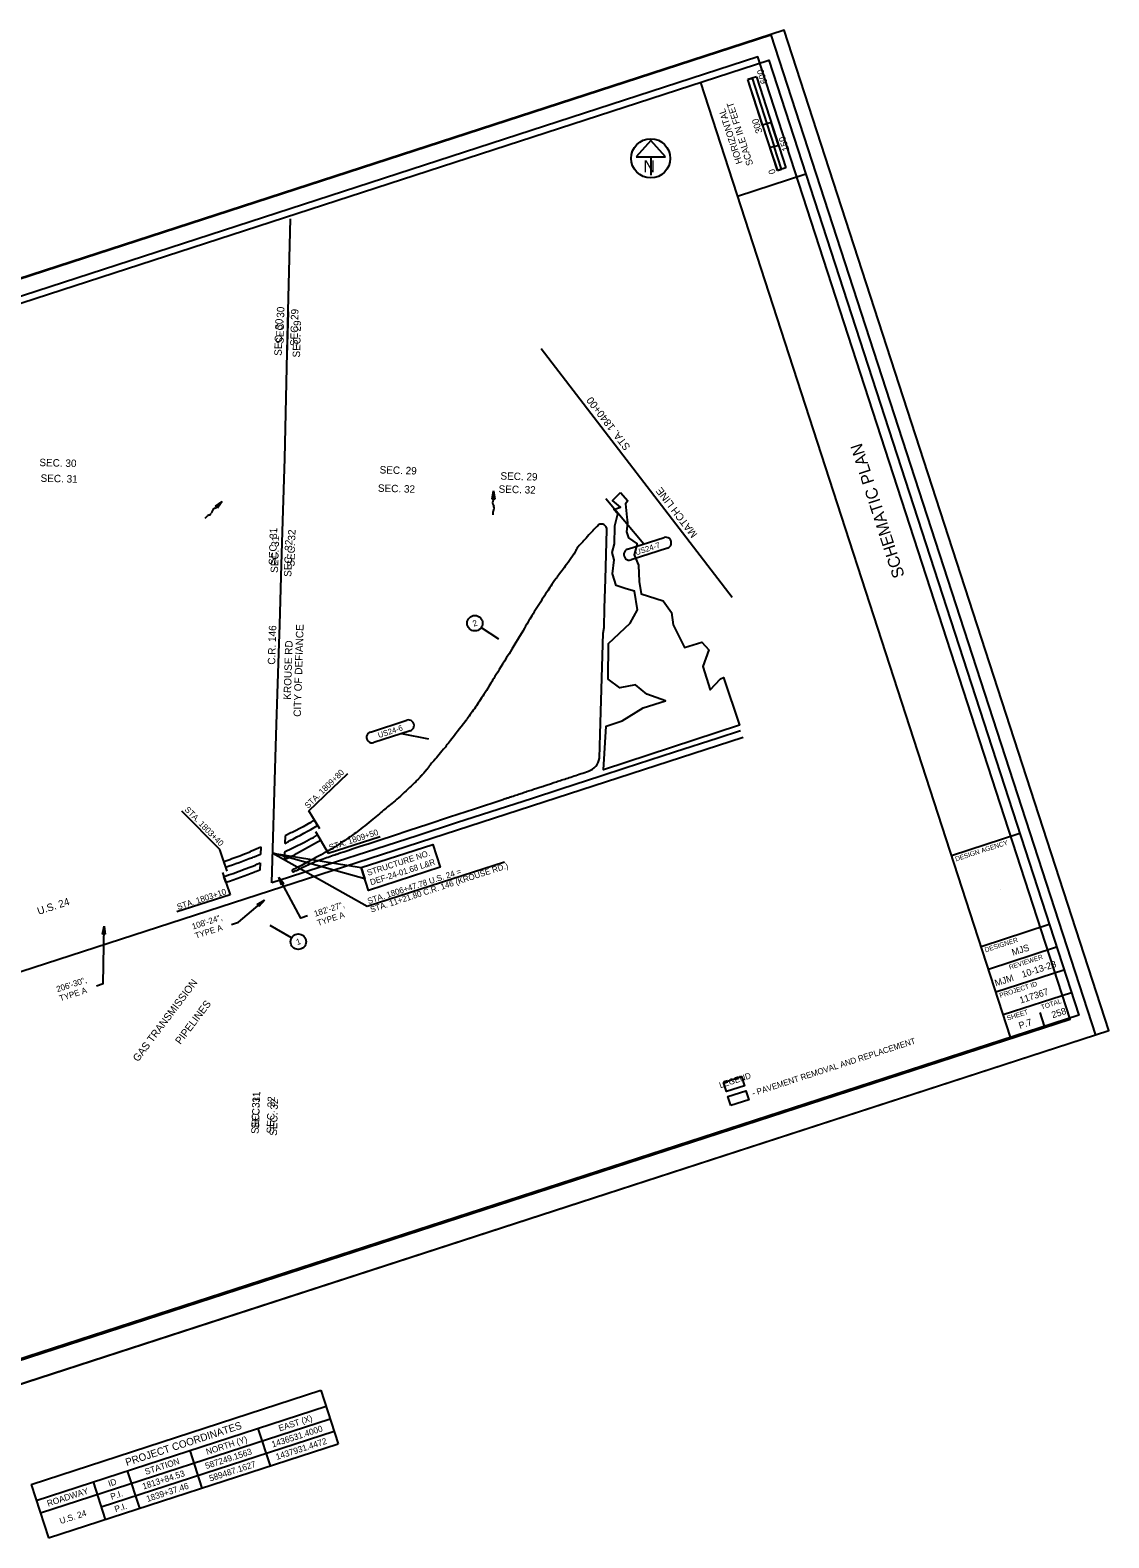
# Model space of a CAD drawing. Extents: x -347516349 to 1482925, y -281753163 to 592205.
# Drawn here: x 1434301 to 1441073, y 582744 to 592205 of the extents above; entities that cross this region are included whole.
import ezdxf

# ---------------------------------------------------------------- set-up
doc = ezdxf.new("R2010")
doc.units = 0
for name, color, linetype in [('DV_X_County_Line', 7, 'Continuous'), ('Level 31', 7, 'Continuous'), ('Level 63', 7, 'Continuous'), ('RD_X_Fence', 7, 'Continuous'), ('RD_X_RR_1', 7, 'Continuous'), ('RW_X_CL', 7, 'Continuous'), ('RW_X_Esmt_CH', 7, 'Continuous'), ('RW_X_Esmt_General', 7, 'Continuous'), ('RW_X_Esmt_LA', 7, 'Continuous'), ('RW_X_Esmt_PB', 7, 'Continuous'), ('RW_X_Fee_RW', 7, 'Continuous'), ('SC_Shading2', 7, 'Continuous'), ('SH_Masking', 7, 'Continuous')]:
    doc.layers.add(name, color=color, linetype=linetype)

msp = doc.modelspace()

# ---------------------------------------------------------------- linework, layer by layer
at = {"layer": 'Level 31'}
for p, q in [((1435464.3, 589216.7), (1435506.9, 589247.1)), ((1435469.4, 589209.6), (1435506.9, 589247.1)), ((1435506.9, 589247.1), (1435476.5, 589204.5)), ((1437201.2, 589262.2), (1437210.9, 589313.6)), ((1437218.3, 589261.9), (1437201.2, 589262.2)), ((1437207.9, 589252.1), (1437206.1, 589248.1)), ((1437209.7, 589260.7), (1437210.9, 589313.6)), ((1437210.9, 589313.6), (1437218.3, 589261.9)), ((1435400.4, 589141.4), (1435415.2, 589156.2)), ((1435426.4, 589162.2), (1435422, 589160.6)), ((1435442.4, 589182.3), (1435439.3, 589174.7)), ((1435446, 589191), (1435442.4, 589182.3)), ((1435462.2, 589204.7), (1435458.1, 589203)), ((1435476.5, 589204.5), (1435464.3, 589216.7)), ((1437205.7, 589231), (1437209.1, 589222.3)), ((1437207.1, 589163.6), (1437207.5, 589184.6)), ((1437209.1, 589222.3), (1437212.1, 589214.6)), ((1437211.4, 589196.7), (1437209.4, 589192.5))]:
    msp.add_line(p, q, dxfattribs=at)
for centre, radius, start, end in [((1437226.6, 589239.1), 22.4, 156.37702, 201.22088), ((1437187.3, 589261.1), 22.4, 336.41585, 358.77587), ((1435428.8, 589142.6), 19.2, 110.52773, 135.01055), ((1435418.6, 589183.2), 22.4, 290.47786, 337.58632), ((1435466.7, 589182.4), 22.4, 112.61169, 157.45555), ((1435453.6, 589225.4), 22.4, 292.65053, 315.01055), ((1437226.7, 589184.2), 19.2, 154.29306, 178.77587), ((1437191.3, 589206.4), 22.4, 334.24318, 21.35164)]:
    msp.add_arc(centre, radius, start, end, dxfattribs=at)
at = {"layer": 'Level 63'}
for points in [[(1429250.2, 589026.2), (1438951, 592175.6), (1440988.8, 585898.9), (1431288, 582749.5)], [(1431356.9, 582923.2), (1440830.2, 585998.8), (1438870, 592036.6), (1429396.7, 588961)]]:
    msp.add_lwpolyline(points, close=True, dxfattribs=at)
at = {"layer": 'RD_X_Fence'}
for p, q in [((1437898, 588420.2), (1437904.1, 588457.1)), ((1436040.3, 586982.6), (1436008.2, 586965.4))]:
    msp.add_line(p, q, dxfattribs=at)
for points in [[(1438007.3, 589304.1), (1438053.9, 589251.1), (1438037.9, 589231.8), (1438048.1, 589147.8), (1438051, 589115.4), (1438044.5, 589056.3), (1438058.4, 589018.6), (1438112.5, 588981.1), (1438093.9, 588913.2), (1438119.4, 588847.8), (1438123.6, 588745.5), (1438137.9, 588668.4), (1438274.5, 588623.4), (1438327.9, 588550), (1438337.9, 588473.4), (1438409.5, 588330), (1438517.9, 588365), (1438561.2, 588316.7), (1438524.5, 588211.7), (1438569.5, 588065), (1438634.5, 588133.4), (1438654, 588141.8), (1438654, 588141.8), (1438654, 588141.8), (1438654, 588141.8), (1438654, 588141.8), (1438753.5, 587842.9), (1438753.5, 587842.9), (1438753.5, 587842.9), (1438753.5, 587842.9), (1437899.9, 587562.5), (1437899.9, 587562.5), (1437899.9, 587562.5), (1437899.9, 587562.5), (1437899.9, 587562.5), (1437899.9, 587562.5), (1437916.6, 587837.1), (1438018.7, 587870.5), (1438149.9, 587951.7), (1438289.5, 587995.5), (1438172.9, 588037.1), (1438102, 588095.5), (1438004.1, 588076.7), (1437929.1, 588133), (1437931.2, 588355.9), (1438068.7, 588483), (1438114.5, 588566.3), (1438096.2, 588685), (1438042.9, 588698.4), (1438043.8, 588698.9), (1437980.5, 588719.3), (1437958.1, 588793), (1437966.7, 588880.7), (1437954.1, 588926.2), (1437970.3, 588981.9), (1437972.4, 589090.4), (1437972.5, 589093.4), (1437991.2, 589168.6), (1437964.7, 589196), (1438007.2, 589211.6), (1437957.1, 589253.8), (1438007.3, 589304.1), (1438007.3, 589304.1)], [(1438653.6, 585600.7), (1438767.7, 585637.7), (1438767.7, 585637.7), (1438767.7, 585637.7), (1438767.7, 585637.7), (1438767.7, 585637.7), (1438786.2, 585580.7), (1438786.2, 585580.7), (1438786.2, 585580.7), (1438786.2, 585580.7), (1438672.1, 585543.6), (1438672.1, 585543.6), (1438672.1, 585543.6), (1438672.1, 585543.6), (1438672.1, 585543.6), (1438672.1, 585543.6), (1438653.6, 585600.7), (1438653.6, 585600.7)]]:
    msp.add_lwpolyline(points, close=True, dxfattribs=at)
for points in [[(1437912.5, 588759.1), (1437921.3, 589068.9)], [(1437907.4, 588577), (1437912.5, 588759.1)], [(1437904.1, 588457.1), (1437907.4, 588577)], [(1437880, 587786.3), (1437898, 588420.2)], [(1437875.7, 587635.3), (1437880, 587786.3)]]:
    msp.add_lwpolyline(points, dxfattribs=at)
for centre, radius, start, end in [((1437887.4, 589071.3), 34, 355.85671, 123.88862), ((1437773.2, 587652.9), 104, 288.82978, 350.29663)]:
    msp.add_arc(centre, radius, start, end, dxfattribs=at)
for points, degree in [([(1437868.5, 589099.5), (1437863.3, 589094.3), (1437848, 589079), (1437818.6, 589048.7), (1437780.9, 589005.6), (1437759.5, 588982.8), (1437745.9, 588966.9), (1437733.9, 588951.1)], 3), ([(1437722.8, 588931), (1437701.8, 588894.8), (1437642.3, 588815.5), (1437619.2, 588785.9), (1437604.7, 588766.1), (1437603.5, 588764.5)], 3), ([(1437733.9, 588951.1), (1437731.2, 588947.3), (1437728, 588941.8), (1437725.9, 588936.5), (1437722.8, 588931)], 2), ([(1437603.5, 588764.5), (1437575.3, 588724.4), (1437549, 588685.3), (1437481, 588578.2), (1437418.5, 588478.8), (1437409.7, 588461.8), (1437393.7, 588433.7)], 3), ([(1437393.3, 588433.1), (1437318.8, 588309.3), (1437250.2, 588199), (1437206, 588126.9), (1437193.8, 588107.2)], 3), ([(1437193.8, 588107.2), (1437164.9, 588060.6), (1437128.1, 588002.4), (1437077.9, 587928.5), (1437040.3, 587877.2), (1437035.8, 587871.1)], 3), ([(1437035.8, 587871.1), (1436993.9, 587815.4), (1436944.5, 587752.2), (1436894.2, 587688.2), (1436860, 587649.6), (1436825.4, 587608.4), (1436806.8, 587586.5), (1436797.4, 587573.5), (1436792.5, 587566.5), (1436791.2, 587564.7)], 3), ([(1436791.2, 587564.7), (1436759.6, 587527.7), (1436755.7, 587523.5), (1436744.7, 587511.5), (1436731.1, 587497.8), (1436716, 587483.2), (1436608.4, 587380.3), (1436534.8, 587322.2), (1436471.7, 587269), (1436358.6, 587175.5), (1436294.4, 587133.1), (1436222, 587082.3), (1436185.1, 587062.3), (1436148.5, 587041.1), (1436113.2, 587021.9), (1436084.1, 587006.6)], 3), ([(1437268.1, 587377.4), (1437412.8, 587425), (1437578.1, 587479.4), (1437806.7, 587554.4)], 2), ([(1436008.2, 586965.4), (1435992.4, 586957.1), (1435964.3, 586943.2), (1435947.7, 586933.6), (1435945.5, 586932.2), (1435945.2, 586931.3), (1435945, 586929.9), (1435948.8, 586924.1), (1435950, 586922.5), (1435950.9, 586922.6), (1435954.4, 586923), (1435989.4, 586939.7), (1436036.7, 586963.5), (1436075.9, 586982.1), (1436133, 587002.3), (1436233.4, 587037.1), (1436256, 587044.4), (1437268.1, 587377.4)], 3), ([(1436084.6, 587006.9), (1436067.1, 586997.2), (1436052.5, 586989.2), (1436040.3, 586982.6)], 2)]:
    msp.add_open_spline(points, degree=degree, dxfattribs=at)
at = {"layer": 'RD_X_RR_1'}
msp.add_line((1431946.9, 585552.1), (1438776.9, 587768.5), dxfattribs=at)
at = {"layer": 'RW_X_CL'}
for p, q in [((1438197.1, 591512.4), (1438104.9, 591410.1)), ((1438289.4, 591410.1), (1438197.1, 591512.4)), ((1438104.9, 591410.1), (1438289.4, 591410.1)), ((1438197.1, 591410.1), (1438197.1, 591294)), ((1438707.4, 588644.4), (1437509.3, 590205.2)), ((1438154.4, 588980.1), (1437915.9, 589263.1)), ((1438052.2, 588947), (1438280.5, 589021.1)), ((1438302.1, 588954.5), (1438073.8, 588880.4)), ((1438302.1, 588954.5), (1438302.1, 588954.5)), ((1437133.7, 588456.4), (1437241.9, 588384.9)), ((1436437.3, 587800.3), (1436665.5, 587874.4)), ((1436687.2, 587807.9), (1436458.9, 587733.8)), ((1436633.1, 587790.3), (1436801.2, 587757.6)), ((1436687.2, 587807.9), (1436687.2, 587807.9)), ((1436051, 587306.4), (1436295.2, 587541)), ((1435491.1, 587062.8), (1435253, 587304.1)), ((1436119, 587192.2), (1436051, 587306.4)), ((1436093.1, 587177), (1436172.9, 587039.8)), ((1436172.9, 587039.8), (1436498.2, 587145.4)), ((1435537.6, 586927.7), (1435491.1, 587062.8)), ((1435824.3, 587039.2), (1436417.6, 586706.8)), ((1436417.6, 586706.8), (1437278.3, 586986.2)), ((1435509.2, 586918), (1435556, 586779.4)), ((1435879.4, 586840.7), (1435862.6, 586890.2)), ((1435862.6, 586890.2), (1435894.5, 586848.8)), ((1435894.5, 586848.8), (1435879.4, 586840.7)), ((1435556, 586779.4), (1435222.7, 586671.2)), ((1435726.7, 586718.4), (1435771.6, 586745.4)), ((1435737.9, 586705.4), (1435726.7, 586718.4)), ((1435771.6, 586745.4), (1435737.9, 586705.4)), ((1434755.8, 586531), (1434765.2, 586582.5)), ((1434773, 586530.8), (1434755.8, 586531)), ((1434759.8, 586219.5), (1434765.2, 586582.5)), ((1434765.2, 586582.5), (1434773, 586530.8)), ((1435942.4, 586509.1), (1435808.4, 586586.9)), ((1434759.8, 586219.5), (1434718.2, 586206)), ((1434307.4, 583078.8), (1436126.4, 583669.4)), ((1436126.4, 583669.4), (1436235.3, 583334.1)), ((1434339.8, 582978.9), (1436158.8, 583569.5)), ((1434365.3, 582900.5), (1436184.3, 583491)), ((1434747.4, 582937.8), (1436209.8, 583412.6)), ((1435730.8, 583430.5), (1435807.3, 583195.1)), ((1434416.2, 582743.5), (1436235.3, 583334.1)), ((1435302.8, 583291.6), (1435379.3, 583056.2)), ((1434910.5, 583164.2), (1434986.9, 582928.8)), ((1434307.4, 583078.8), (1434416.2, 582743.5)), ((1434696.5, 583094.7), (1434772.9, 582859.3))]:
    msp.add_line(p, q, dxfattribs=at)
for points in [[(1436379.7, 586949.5), (1436829.4, 587095.5), (1436875.7, 586952.8), (1436426, 586806.8)], [(1436402.9, 586878), (1435824.3, 587039.2), (1436379.7, 586949.5)]]:
    msp.add_lwpolyline(points, close=True, dxfattribs=at)
for points in [[(1436041.8, 586645.9), (1436000.9, 586632.7), (1435862.6, 586890.2)], [(1435565.1, 586593), (1435610, 586607.6), (1435771.6, 586745.4)]]:
    msp.add_lwpolyline(points, dxfattribs=at)
for centre, radius in [((1438197.1, 591400.3), 123), ((1437093, 588483.2), 48.8), ((1435984.6, 586484.6), 48.8)]:
    msp.add_circle(centre, radius, dxfattribs=at)
for centre, start, end in [((1438291.3, 588987.8), 287.98598, 107.9864), ((1438063, 588913.7), 107.9864, 287.98682), ((1436676.4, 587841.2), 287.98598, 107.9864), ((1436448.1, 587767), 107.9864, 287.98682)]:
    msp.add_arc(centre, 35, start, end, dxfattribs=at)
at = {"layer": 'RW_X_Esmt_CH'}
for p, q in [((1438860.5, 591911.5), (1438807, 591894.1)), ((1438807, 591894.1), (1438833.6, 591902.8)), ((1438833.6, 591902.8), (1438833.8, 591902.8)), ((1438833.8, 591902.8), (1438926.5, 591617.5)), ((1438860.5, 591911.5), (1439045.7, 591340.8)), ((1438992.2, 591323.4), (1438807, 591894.1)), ((1438899.6, 591608.8), (1438807, 591894.1)), ((1438926.5, 591617.5), (1438899.6, 591608.8)), ((1438952.9, 591626.1), (1438926.2, 591617.4)), ((1438926.2, 591617.4), (1438972.6, 591474.7)), ((1438999.2, 591483.4), (1438952.9, 591626.1)), ((1438972.6, 591474.7), (1438945.9, 591466.1)), ((1438945.9, 591466.1), (1438992.2, 591323.4)), ((1438972.6, 591474.7), (1438999.2, 591483.4)), ((1439018.9, 591332.1), (1438972.6, 591474.7)), ((1439045.7, 591340.8), (1438992.2, 591323.4)), ((1438992.2, 591323.4), (1439018.9, 591332.1)), ((1440392.3, 586810.2), (1440392.3, 586810.2)), ((1440670.2, 585954.2), (1440642.4, 586039.8)), ((1440547, 585969.4), (1440547, 585969.4))]:
    msp.add_line(p, q, dxfattribs=at)
at = {"layer": 'RW_X_Esmt_General'}
for p, q in [((1440456.2, 585884.7), (1438510.8, 591876.8)), ((1438742.4, 591163.5), (1439170.4, 591302.4)), ((1440085.7, 587026.1), (1440513.7, 587165)), ((1440270.9, 586455.4), (1440699, 586594.3)), ((1440317.3, 586312.7), (1440745.3, 586451.7)), ((1440363.6, 586170), (1440791.6, 586309)), ((1440409.9, 586027.4), (1440837.9, 586166.3))]:
    msp.add_line(p, q, dxfattribs=at)
msp.add_lwpolyline([(1429808, 589051.4), (1438938.8, 592015.8), (1440884.2, 586023.7), (1431753.4, 583059.3)], close=True, dxfattribs=at)
at = {"layer": 'RW_X_Esmt_PB'}
msp.add_lwpolyline([(1431371.7, 582777.6), (1441073.2, 585927.3), (1439035.2, 592204.8), (1429333.7, 589055.1)], close=True, dxfattribs=at)
at = {"layer": 'RW_X_Fee_RW'}
for p, q in [((1435917.5, 590278.9), (1435935, 591020.5)), ((1435914.3, 590161.4), (1435922.9, 590437.4)), ((1435899.5, 589516.9), (1435917.5, 590278.9)), ((1435888.2, 589125.2), (1435899.5, 589516.9)), ((1435879.7, 588849.2), (1435888.2, 589125.2)), ((1435875.1, 588700.5), (1435879.7, 588849.2)), ((1435868, 588473.2), (1435875.1, 588700.5)), ((1435862.6, 588295.6), (1435868, 588473.2)), ((1435854.6, 588039.8), (1435862.6, 588295.6)), ((1435848.7, 587847.1), (1435854.6, 588039.8)), ((1435842.3, 587641.3), (1435848.7, 587847.1)), ((1438620.6, 587762.2), (1438347.2, 587673.5)), ((1438760.8, 587807.6), (1438620.6, 587762.2)), ((1435817.8, 586853.4), (1435842.3, 587641.3)), ((1438347.2, 587673.5), (1438036.2, 587572.7)), ((1438036.2, 587572.7), (1437883.3, 587523.1)), ((1437883.3, 587523.1), (1437632.3, 587441.8)), ((1437447.7, 587381.9), (1436985, 587231.9)), ((1437632.3, 587441.8), (1437447.7, 587381.9)), ((1436985, 587231.9), (1436729.9, 587149.2)), ((1436729.9, 587149.2), (1436411.9, 587046.1)), ((1436231.7, 586987.6), (1435929.5, 586889.7)), ((1436411.9, 587046.1), (1436231.7, 586987.6)), ((1435929.5, 586889.7), (1435817.9, 586853.5))]:
    msp.add_line(p, q, dxfattribs=at)
at = {"layer": 'SC_Shading2'}
for p, q in [((1435937.4, 587166.9), (1435902.3, 587149.1)), ((1435947.1, 587169.7), (1435937.4, 587166.9)), ((1436014.6, 587206), (1435947.1, 587169.7)), ((1436057.1, 587230.1), (1436014.6, 587206)), ((1436105.7, 587214.6), (1436086.3, 587247.2)), ((1435691.4, 587054.6), (1435749.4, 587079.1)), ((1435749.4, 587079.1), (1435747.7, 587032.3)), ((1435749.4, 587079.1), (1435749.4, 587079.1)), ((1435902.3, 587149.1), (1435900.6, 587101.4)), ((1435900.6, 587101.4), (1435924.1, 587113)), ((1435902.3, 587149.1), (1435902.3, 587149.1)), ((1435924.1, 587113), (1435932.1, 587119.3)), ((1435955.4, 587072.8), (1435945.5, 587070.1)), ((1436023, 587108), (1435955.4, 587072.8)), ((1436052.5, 587124.1), (1436023, 587108)), ((1436125.3, 587121.7), (1436106.2, 587154.5)), ((1435529.1, 586952.3), (1435516.8, 586988.2)), ((1435617.2, 587024), (1435647.7, 587035.5)), ((1435647.7, 587035.5), (1435682.8, 587049.1)), ((1435682.8, 587049.1), (1435691.4, 587054.6)), ((1435706.9, 587015.6), (1435696.9, 587013.8)), ((1435747.7, 587032.3), (1435706.9, 587015.6)), ((1435724.7, 586971.1), (1435745.9, 586979.6)), ((1435745.9, 586979.6), (1435744.2, 586933.6)), ((1435745.9, 586979.6), (1435745.9, 586979.6)), ((1435898.7, 587047.2), (1435897.1, 587000)), ((1435897.1, 587000), (1435964.3, 587032.5)), ((1435945.5, 587070.1), (1435898.7, 587047.2)), ((1435898.7, 587047.2), (1435898.7, 587047.2)), ((1435964.3, 587032.5), (1435972.4, 587038.8)), ((1435529.6, 586857.4), (1435517.5, 586893.4)), ((1435575.8, 586913.5), (1435651.7, 586940.8)), ((1435651.7, 586940.8), (1435716.2, 586965.5)), ((1435722.5, 586925), (1435712.4, 586923.2)), ((1435716.2, 586965.5), (1435724.7, 586971.1)), ((1435744.2, 586933.6), (1435722.5, 586925))]:
    msp.add_line(p, q, dxfattribs=at)
msp.add_lwpolyline([(1438699.3, 585455.6), (1438680.8, 585512.7), (1438794.9, 585549.7), (1438813.4, 585492.6)], close=True, dxfattribs=at)
for centre, radius, start, end in [((1434697.5, 589574.7), 2748.3, 296.69425, 300.82303), ((1434736.1, 589515.1), 2639.3, 300.03424, 300.76793), ((1332336.5, 778448.4), 217665, 298.432652, 298.47844), ((1434653.9, 589654.1), 2890.8, 298.93436, 300.15723), ((1434066.8, 591217.7), 4471.1, 288.92222, 290.28834), ((1434256.8, 590682.4), 3941.1, 288.83448, 291.43292), ((1434858.9, 588902.3), 2114.1, 288.15058, 289.82274), ((1434235.3, 590737.2), 4090.1, 288.44957, 291.1713)]:
    msp.add_arc(centre, radius, start, end, dxfattribs=at)
at = {"layer": 'SH_Masking'}
msp.add_circle((1438197.1, 591400.3), 123, dxfattribs=at)

# ---------------------------------------------------------------- texts
at = {"layer": 'DV_X_County_Line'}
for s, rotation, p in [('GAS TRANSMISSION', 53.0555, (1434978.8, 585727.5)), ('PIPELINES', 52.88975, (1435244.7, 585836))]:
    msp.add_text(s, height=46.8, rotation=rotation, dxfattribs=at).set_placement(p)
at = {"layer": 'RW_X_CL'}
for s, height, rotation, p in [('N', 75, 0.00095, (1438151.8, 591312.9)), ('SEC. 30', 46.8, 88.29036, (1435880.3, 590160.6)), ('SEC. 29', 46.8, 88.29036, (1435995.3, 590149.7)), ('MATCH LINE                  STA. 1840+00', 46.8, 127.51131, (1438493, 589041.1)), ('SEC. 29', 46.8, 358.29036, (1436494.7, 589423.1)), ('SEC. 32', 46.8, 358.29036, (1436483.8, 589308.1)), ('SEC. 31', 46.8, 88.29036, (1435845.7, 588848.4)), ('SEC. 32', 46.8, 88.29036, (1435960.7, 588837.5)), ('US24-7', 35.5, 17.9864, (1438106.4, 588909.1)), ('2', 37.5, 17.9864, (1437086.2, 588461.3)), ('C.R. 146', 46.8, 88.29036, (1435839.4, 588222.2)), ('CITY OF DEFIANCE', 46.8, 88.29036, (1436000.9, 587895.3)), ('KROUSE RD', 46.8, 88.29036, (1435938.2, 588002.8)), ('US24-6', 35.5, 17.9864, (1436490.9, 587762.3)), ('STA. 1809+80', 37.5, 44.43185, (1436045.8, 587317.5)), ('STA. 1803+40', 37.5, 314.43185, (1435268.2, 587310.3)), ('STA. 1809+50', 37.5, 17.9864, (1436183.9, 587056.7)), ('STRUCTURE NO.', 37.5, 17.9864, (1436422.8, 586897.8)), ('DEF-24-01.68 L&R', 37.5, 17.9864, (1436442.1, 586838.3)), ('STA. 11+21.80 C.R. 146 (KROUSE RD.)', 37.5, 17.9864, (1436443.2, 586666.8)), ('STA. 1806+47.78 U.S. 24 =', 37.5, 17.9864, (1436425.8, 586720.4)), ('STA. 1803+10', 37.5, 17.9864, (1435230.1, 586683.9)), ('U.S. 24', 46.8, 17.98637, (1434354.7, 586652.6)), ('182\'-27",', 37.5, 17.9864, (1436090.6, 586641.1)), ('108\'-24",', 37.5, 17.9864, (1435323.8, 586560.6)), ('TYPE A', 37.5, 17.9864, (1436109.4, 586583.2)), ('TYPE A', 37.5, 17.9864, (1435342.6, 586502.7)), ('1', 37.5, 17.9864, (1435977.8, 586462.7)), ('206\'-30",', 37.5, 17.9864, (1434472.7, 586167.4)), ('TYPE A', 37.5, 17.9864, (1434491.5, 586109.5)), ('- PAVEMENT REMOVAL AND REPLACEMENT', 37.5, 17.9864, (1438839.9, 585514.6)), ('LEGEND', 37.5, 17.9864, (1438634, 585564.9)), ('SEC. 31', 46.8, 88.29036, (1435735.7, 585277.4)), ('SEC. 32', 46.8, 88.29036, (1435850.7, 585266.5)), ('EAST (X)', 39, 17.9864, (1435867.7, 583411.1)), ('PROJECT COORDINATES', 46.5, 17.9864, (1434907.9, 583194.1)), ('NORTH (Y)', 39, 17.9864, (1435412.7, 583263.4)), ('1436531.4000', 39, 17.9864, (1435824.2, 583310.2)), ('587249.1563', 39, 17.9864, (1435407.4, 583174.9)), ('1437931.4472', 39, 17.9864, (1435850.3, 583232)), ('STATION', 39, 17.9864, (1435028.2, 583138.6)), ('589487.1627', 39, 17.9864, (1435432.5, 583096.3)), ('ID', 39, 17.9864, (1434798.2, 583063.9)), ('1813+84.53', 39, 17.9864, (1435012.3, 583046.6)), ('ROADWAY', 39, 17.9864, (1434414.4, 582939.3)), ('P.I.', 39, 17.9864, (1434812.6, 582981.8)), ('1839+37.46', 39, 17.9864, (1435037.2, 582968)), ('U.S. 24', 39, 17.9864, (1434493.1, 582829.3)), ('P.I.', 39, 17.9864, (1434838.1, 582903.4))]:
    msp.add_text(s, height=height, rotation=rotation, dxfattribs=at).set_placement(p)
at = {"layer": 'RW_X_Esmt_CH'}
for s, height, rotation, p in [('600', 42, 107.9864, (1438931, 591875.1)), ('HORIZONTAL', 42, 107.9864, (1438773.9, 591372.5)), ('SCALE IN FEET', 42, 107.9864, (1438841.1, 591362.4)), ('300', 42, 107.9864, (1438899.2, 591565.1)), ('150', 42, 107.9864, (1439068.1, 591452.8)), ('0', 42, 107.9864, (1438982.7, 591308.1)), ('SCHEMATIC PLAN', 75, 107.9864, (1439792.1, 588780.5)), ('DESIGN AGENCY', 30, 17.9864, (1440113.8, 586987.9)), ('DESIGNER', 30, 17.9864, (1440299.1, 586417.2)), ('MJS', 42, 17.9864, (1440471.3, 586395.8)), ('REVIEWER', 30, 17.9864, (1440451.5, 586309)), ('10-13-23', 42, 17.9864, (1440533.3, 586258.3)), ('MJM', 42, 17.9864, (1440364, 586203.3)), ('PROJECT ID', 30, 17.9864, (1440391.7, 586131.9)), ('117367', 42, 17.9864, (1440520, 586096.2)), ('SHEET', 30, 17.9864, (1440438.1, 585989.2)), ('TOTAL', 30, 17.9864, (1440652.1, 586058.7)), ('258', 42, 17.9864, (1440721, 586003.8)), ('P.7', 42, 17.9864, (1440514.8, 585936.8))]:
    msp.add_text(s, height=height, rotation=rotation, dxfattribs=at).set_placement(p)
at = {"layer": 'RW_X_Esmt_LA'}
for s, rotation, p in [('SEC. 30', 88.64544, (1435891.8, 590236.1)), ('SEC. 29', 88.64544, (1435980.4, 590222)), ('SEC. 30', 358.41626, (1434358.7, 589469.1)), ('SEC. 31', 358.41626, (1434366.2, 589370.7)), ('SEC. 32', 358.46784, (1437241.7, 589302.1)), ('SEC. 29', 358.46784, (1437253.1, 589384.4)), ('SEC. 31', 88.22724, (1435857.1, 588798.7)), ('SEC. 32', 88.22724, (1435941, 588773.6)), ('SEC. 31', 88.22724, (1435738.5, 585310.5)), ('SEC. 32', 88.22724, (1435832.1, 585280.4))]:
    msp.add_text(s, height=46.8, rotation=rotation, dxfattribs=at).set_placement(p)

doc.saveas('drawing.dxf')
